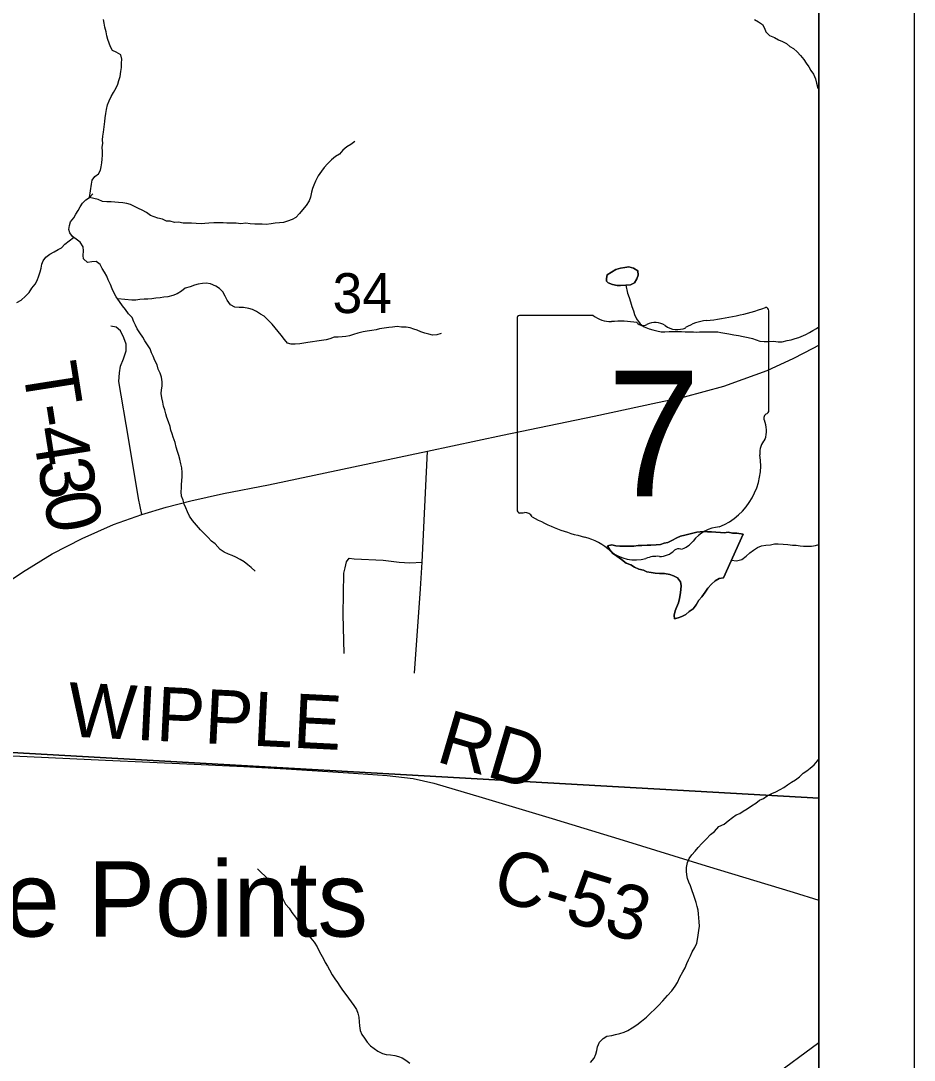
# Model space of a CAD drawing. Extents: x -20.2 to 34, y 0 to 22.
# Drawn here: x 8.064 to 9, y 15.546 to 16.636 of the extents above; entities that cross this region are included whole.
import ezdxf

# ---------------------------------------------------------------- set-up
doc = ezdxf.new("R2010")
doc.units = 0
for name, color, linetype in [('Default', 7, 'Continuous'), ('GM_X_County_Road', 7, 'Continuous'), ('GM_X_County_Road_Text', 7, 'Continuous'), ('GM_X_Minor_River', 7, 'Continuous'), ('GM_X_Section_Text', 7, 'Continuous'), ('GM_X_State_Location', 7, 'Continuous'), ('GM_X_State_Route', 7, 'Continuous'), ('GM_X_State_Shield', 7, 'Continuous'), ('GM_X_Township_Road', 7, 'Continuous'), ('GM_X_Township_Road_Text', 7, 'Continuous'), ('GM_X_Unincorporated_Text', 7, 'Continuous'), ('SH_Cut_Line', 7, 'Continuous'), ('SH_Data', 7, 'Continuous')]:
    doc.layers.add(name, color=color, linetype=linetype)

msp = doc.modelspace()

# ---------------------------------------------------------------- linework, layer by layer
at = {"layer": 'Default'}
msp.add_lwpolyline([(7.8018, 14.8755), (8.7518, 14.8242), (8.8043, 14.8205), (8.8307, 14.8199), (8.9, 14.8176), (8.9, 20.9)], dxfattribs=at)
for points in [[(8.9, 15.8211), (8.9, 16.8537), (7.92, 16.8975), (7.8624, 15.8798)], [(8.9, 15.3734), (8.9, 15.8211), (7.8624, 15.8798), (7.7985, 14.8753), (8.8697, 14.8191)]]:
    msp.add_lwpolyline(points, close=True, dxfattribs=at)
at = {"layer": 'GM_X_County_Road'}
for points in [[(7.897, 15.8728), (7.9034, 15.8722), (7.9138, 15.8722), (7.9584, 15.8698), (8.0532, 15.8653), (8.0554, 15.8652), (8.1524, 15.8608), (8.2454, 15.8566), (8.2975, 15.854), (8.3417, 15.8516), (8.407, 15.8476), (8.4477, 15.8447), (8.4747, 15.8414), (8.4965, 15.8366), (8.547, 15.8215), (8.6207, 15.7995), (8.695, 15.7768), (8.7819, 15.7502), (8.8731, 15.7225), (8.9, 15.7139)], [(8.8507, 15.5286), (8.9, 15.565)]]:
    msp.add_lwpolyline(points, dxfattribs=at)
at = {"layer": 'GM_X_Minor_River'}
for points in [[(8.1357, 16.4506), (8.1377, 16.4644), (8.1384, 16.4686), (8.1411, 16.4724), (8.1452, 16.4751), (8.1471, 16.4789), (8.1478, 16.4827), (8.1485, 16.4869), (8.1488, 16.4907), (8.1491, 16.4949), (8.1491, 16.4987), (8.149, 16.5032), (8.1494, 16.507), (8.1493, 16.5108), (8.1497, 16.5146), (8.1504, 16.5188), (8.1511, 16.5245), (8.1518, 16.5299), (8.1521, 16.534), (8.1528, 16.5386), (8.1535, 16.5428), (8.1546, 16.5474), (8.1561, 16.5516), (8.1583, 16.5562), (8.1609, 16.5604), (8.1635, 16.5653), (8.1654, 16.5692), (8.1665, 16.573), (8.1679, 16.5772), (8.1686, 16.5825), (8.169, 16.5867), (8.1693, 16.5912), (8.1696, 16.5954), (8.1684, 16.6), (8.1634, 16.6029), (8.1596, 16.6044), (8.1577, 16.6082), (8.1561, 16.612), (8.1549, 16.6161), (8.1538, 16.6199), (8.153, 16.6241), (8.1518, 16.629), (8.1509, 16.6332), (8.1501, 16.637)], [(8.8326, 16.6368), (8.8368, 16.6346), (8.8411, 16.6316), (8.843, 16.6278), (8.8446, 16.624), (8.8484, 16.6203), (8.8534, 16.6181), (8.8576, 16.6158), (8.8621, 16.614), (8.866, 16.6118), (8.8698, 16.6088), (8.8736, 16.6065), (8.8774, 16.6032), (8.8809, 16.5994), (8.8844, 16.5949), (8.8867, 16.5911), (8.8894, 16.5874), (8.8917, 16.5836), (8.8944, 16.5798), (8.8964, 16.5749), (8.8976, 16.5704), (8.8991, 16.5651), (8.9, 16.5637)], [(8.4136, 16.5092), (8.4094, 16.5061), (8.4053, 16.5034), (8.4011, 16.4999), (8.3978, 16.4957), (8.3936, 16.4934), (8.3891, 16.4899), (8.385, 16.4857), (8.3816, 16.4819), (8.3786, 16.478), (8.3753, 16.473), (8.3723, 16.4677), (8.3708, 16.4635), (8.3693, 16.4597), (8.3682, 16.4559), (8.3672, 16.4509), (8.3657, 16.4471), (8.3627, 16.4421), (8.359, 16.4375), (8.3556, 16.4337), (8.3519, 16.4294), (8.3481, 16.4275), (8.3432, 16.4255), (8.339, 16.4243), (8.3348, 16.4239), (8.3303, 16.4235), (8.3261, 16.4227), (8.3208, 16.4222), (8.3166, 16.4225), (8.3128, 16.4225), (8.309, 16.4225), (8.3041, 16.4228), (8.2995, 16.4235), (8.2942, 16.423), (8.2893, 16.4237), (8.2851, 16.4237), (8.2794, 16.4236), (8.2756, 16.4239), (8.2711, 16.4239), (8.2658, 16.4238), (8.2608, 16.4234), (8.2566, 16.4233), (8.2525, 16.4229), (8.2475, 16.4232), (8.2426, 16.4235), (8.2384, 16.4235), (8.2339, 16.4234), (8.2289, 16.4245), (8.2247, 16.4244), (8.2202, 16.4255), (8.2164, 16.4258), (8.2122, 16.4277), (8.2072, 16.4288), (8.2034, 16.4302), (8.1996, 16.4317), (8.1954, 16.4347), (8.1908, 16.4373), (8.187, 16.4388), (8.1828, 16.441), (8.1786, 16.4432), (8.1748, 16.4443), (8.1706, 16.445), (8.166, 16.4453), (8.1622, 16.4457), (8.1584, 16.446), (8.1539, 16.446), (8.1493, 16.4463), (8.1448, 16.4485), (8.1357, 16.4506)], [(8.3094, 16.0588), (8.3052, 16.0626), (8.3014, 16.0656), (8.2976, 16.0686), (8.2934, 16.0712), (8.2888, 16.0735), (8.285, 16.0753), (8.2812, 16.0765), (8.2766, 16.0787), (8.2724, 16.0817), (8.2674, 16.0874), (8.2636, 16.0904), (8.2598, 16.0945), (8.256, 16.0979), (8.2521, 16.1021), (8.2479, 16.107), (8.2437, 16.1119), (8.2403, 16.1164), (8.2383, 16.121), (8.2364, 16.1251), (8.2349, 16.1289), (8.2337, 16.1331), (8.2321, 16.1376), (8.2317, 16.1418), (8.2321, 16.146), (8.232, 16.1498), (8.2324, 16.1536), (8.2327, 16.1581), (8.2327, 16.1623), (8.2323, 16.1672), (8.2315, 16.1714), (8.2303, 16.1763), (8.2292, 16.1801), (8.228, 16.1843), (8.2264, 16.1889), (8.2253, 16.1938), (8.2233, 16.1991), (8.2222, 16.2029), (8.221, 16.2067), (8.2202, 16.2105), (8.2183, 16.2154), (8.2167, 16.2199), (8.2156, 16.2237), (8.2144, 16.2279), (8.2132, 16.2317), (8.2124, 16.2358), (8.2113, 16.2404), (8.2108, 16.2449), (8.2112, 16.2487), (8.2119, 16.2526), (8.2119, 16.2571), (8.2111, 16.262), (8.2095, 16.2662), (8.2076, 16.2707), (8.2064, 16.2749), (8.2041, 16.2795), (8.2022, 16.284), (8.2007, 16.2878), (8.1991, 16.292), (8.1964, 16.2961), (8.1937, 16.3003), (8.1914, 16.3041), (8.1884, 16.3086), (8.1857, 16.3127), (8.1837, 16.3165), (8.1822, 16.3203), (8.1803, 16.3245), (8.1764, 16.3286), (8.1734, 16.3332), (8.1703, 16.3369), (8.1672, 16.3415), (8.1634, 16.3464), (8.1615, 16.3502), (8.1592, 16.3547), (8.1576, 16.3593), (8.1553, 16.3642), (8.1537, 16.368), (8.1514, 16.3721), (8.1488, 16.3759), (8.1468, 16.3801), (8.1426, 16.3835), (8.1381, 16.383), (8.1335, 16.3823), (8.1293, 16.386), (8.1289, 16.3898), (8.1293, 16.3944), (8.1288, 16.3989), (8.1258, 16.4035), (8.1216, 16.4069), (8.1177, 16.4095), (8.1151, 16.4133), (8.1139, 16.417), (8.1146, 16.4212), (8.1157, 16.425), (8.1191, 16.4292), (8.1214, 16.4331), (8.1236, 16.4369), (8.1259, 16.4407), (8.1281, 16.4445), (8.1319, 16.4479), (8.1357, 16.4506)], [(8.1357, 16.4506), (8.1391, 16.4544)], [(8.0639, 16.343), (8.0685, 16.3472), (8.0722, 16.3507), (8.0752, 16.3553), (8.0786, 16.3595), (8.0809, 16.3636), (8.0824, 16.3682), (8.0838, 16.3724), (8.085, 16.3762), (8.0857, 16.3804), (8.0872, 16.3842), (8.0898, 16.388), (8.094, 16.3911), (8.0985, 16.3934), (8.1027, 16.3961), (8.1064, 16.3976), (8.1098, 16.4014), (8.119, 16.4086)], [(8.6979, 16.3586), (8.6922, 16.3581), (8.6885, 16.3581), (8.6839, 16.3592), (8.6793, 16.3611), (8.6775, 16.3629), (8.6774, 16.3656), (8.6781, 16.3694), (8.6827, 16.3721), (8.6872, 16.3748), (8.6921, 16.3764), (8.6967, 16.3772), (8.701, 16.3776), (8.7058, 16.3765), (8.7104, 16.3735), (8.7108, 16.3689), (8.7093, 16.3651), (8.7067, 16.3609), (8.7025, 16.359), (8.6979, 16.3586)], [(8.6872, 16.3748), (8.6827, 16.3721), (8.6781, 16.3694), (8.6774, 16.3656), (8.6775, 16.3629), (8.6793, 16.3611), (8.6839, 16.3592), (8.6885, 16.3581), (8.6922, 16.3581), (8.6979, 16.3586)], [(8.6979, 16.3586), (8.7025, 16.359), (8.7067, 16.3609), (8.7093, 16.3651), (8.7108, 16.3689), (8.7104, 16.3735), (8.7058, 16.3765), (8.701, 16.3776), (8.6967, 16.3772), (8.6921, 16.3764), (8.6872, 16.3748)], [(8.5043, 16.3078), (8.4997, 16.3066), (8.4952, 16.3062), (8.4914, 16.3073), (8.4872, 16.3084), (8.483, 16.3096), (8.4792, 16.3114), (8.4754, 16.3125), (8.4716, 16.3137), (8.4674, 16.3144), (8.4625, 16.3147), (8.4579, 16.3151), (8.4533, 16.3147), (8.4492, 16.3143), (8.4446, 16.3135), (8.4397, 16.3127), (8.4359, 16.3119), (8.4314, 16.3111), (8.4268, 16.3103), (8.4226, 16.3095), (8.4169, 16.3083), (8.4124, 16.3068), (8.4082, 16.3056), (8.4044, 16.3048), (8.4003, 16.3044), (8.3961, 16.304), (8.3919, 16.304), (8.3874, 16.3024), (8.3836, 16.3012), (8.3787, 16.3005), (8.3737, 16.3), (8.3692, 16.2992), (8.3646, 16.2985), (8.3604, 16.2977), (8.3559, 16.2969), (8.3513, 16.2968), (8.3468, 16.2968), (8.343, 16.2979), (8.3399, 16.3017), (8.3365, 16.3062), (8.3334, 16.31), (8.3303, 16.3138), (8.3269, 16.3176), (8.3223, 16.3225), (8.3188, 16.3262), (8.315, 16.3281), (8.3105, 16.3311), (8.3066, 16.333), (8.3025, 16.3341), (8.2971, 16.3352), (8.2926, 16.3352), (8.288, 16.3355), (8.2834, 16.3378), (8.28, 16.343), (8.2777, 16.3472), (8.2754, 16.3514), (8.2719, 16.3551), (8.2681, 16.3574), (8.2624, 16.36), (8.2578, 16.3607), (8.254, 16.3603), (8.2495, 16.3595), (8.2457, 16.3587), (8.2412, 16.3568), (8.2359, 16.3553), (8.2321, 16.3522), (8.2275, 16.3495), (8.223, 16.3476), (8.2177, 16.3464), (8.2135, 16.346), (8.2097, 16.3452), (8.2052, 16.3448), (8.201, 16.3444), (8.1968, 16.344), (8.193, 16.3439), (8.1885, 16.3435), (8.1843, 16.3427), (8.1801, 16.3427), (8.1652, 16.3441)], [(8.6979, 16.3586), (8.6995, 16.3502), (8.7011, 16.3457), (8.7026, 16.3411), (8.7042, 16.3362), (8.7057, 16.3317), (8.7069, 16.3279), (8.7088, 16.3233), (8.7127, 16.318), (8.7169, 16.315), (8.7222, 16.3128), (8.726, 16.3117), (8.7302, 16.3106), (8.7348, 16.3098), (8.7386, 16.3095), (8.7431, 16.3099), (8.7473, 16.3099), (8.7511, 16.31), (8.756, 16.31), (8.7598, 16.3096), (8.7644, 16.3097), (8.7685, 16.3097), (8.7723, 16.3093), (8.7748, 16.3097), (8.7803, 16.3098), (8.7856, 16.3098), (8.7902, 16.3098), (8.794, 16.3095), (8.7973, 16.3089), (8.8016, 16.3084), (8.8058, 16.3077), (8.8111, 16.3066), (8.8157, 16.3059), (8.8206, 16.3048), (8.8259, 16.3036), (8.8305, 16.3025), (8.8343, 16.3011), (8.8381, 16.2999), (8.8427, 16.2996), (8.8476, 16.2996), (8.8525, 16.2997), (8.8575, 16.2993), (8.8617, 16.2993), (8.867, 16.3005), (8.8711, 16.3013), (8.8753, 16.3025), (8.8791, 16.3036), (8.8863, 16.3067), (8.8901, 16.309), (8.8938, 16.311), (8.8976, 16.3133), (8.9, 16.3148)], [(8.0594, 16.3403), (8.0639, 16.343)], [(8.8206, 16.0977), (8.8141, 16.0985), (8.8096, 16.0988), (8.805, 16.0996), (8.8008, 16.0991), (8.797, 16.0995), (8.7921, 16.0998), (8.7875, 16.1002), (8.7834, 16.1002), (8.7796, 16.1005), (8.7758, 16.1001), (8.772, 16.0997), (8.7678, 16.0985), (8.7636, 16.0977), (8.7595, 16.0966), (8.7549, 16.0954), (8.7511, 16.0939), (8.7458, 16.0908), (8.7417, 16.0888), (8.7379, 16.0881), (8.7341, 16.0869), (8.7296, 16.0865), (8.7239, 16.0861), (8.7201, 16.086), (8.7144, 16.0856), (8.7106, 16.0856), (8.706, 16.0852), (8.7011, 16.0851), (8.6961, 16.0851), (8.6916, 16.0851), (8.6874, 16.0854), (8.6832, 16.0865), (8.6787, 16.0854), (8.681, 16.0812), (8.6841, 16.0774), (8.6883, 16.0744), (8.6932, 16.071), (8.6982, 16.0673)], [(8.8206, 16.0977), (8.8001, 16.052), (8.7955, 16.0513), (8.7913, 16.0486), (8.7876, 16.0451), (8.7838, 16.0409), (8.7808, 16.0367), (8.7774, 16.0321), (8.7744, 16.0283), (8.7714, 16.0234), (8.7684, 16.0195), (8.7642, 16.0165), (8.7605, 16.0134), (8.7563, 16.0115), (8.7525, 16.0099), (8.7487, 16.0088), (8.7483, 16.0126), (8.7494, 16.0171), (8.7509, 16.0209), (8.7528, 16.0255), (8.7539, 16.0301), (8.7546, 16.0339), (8.7553, 16.0392), (8.7557, 16.0438), (8.7549, 16.0475), (8.7518, 16.0517), (8.7476, 16.0539), (8.7438, 16.0554), (8.7381, 16.0565), (8.7332, 16.0565), (8.7286, 16.0569), (8.7244, 16.0576), (8.7199, 16.0583), (8.7161, 16.0598), (8.7115, 16.0609), (8.7069, 16.0632), (8.7031, 16.0654), (8.6982, 16.0673), (8.6932, 16.071), (8.6883, 16.0744), (8.6841, 16.0774), (8.681, 16.0812), (8.6787, 16.0854), (8.6832, 16.0865), (8.6874, 16.0854), (8.6916, 16.0851), (8.6961, 16.0851), (8.7011, 16.0851), (8.706, 16.0852), (8.7106, 16.0856), (8.7144, 16.0856), (8.7201, 16.086), (8.7239, 16.0861), (8.7296, 16.0865), (8.7341, 16.0869), (8.7379, 16.0881), (8.7417, 16.0888), (8.7458, 16.0908), (8.7511, 16.0939), (8.7549, 16.0954), (8.7595, 16.0966), (8.7636, 16.0977), (8.7678, 16.0985), (8.772, 16.0997), (8.7758, 16.1001), (8.7796, 16.1005), (8.7834, 16.1002), (8.7875, 16.1002), (8.7921, 16.0998), (8.797, 16.0995), (8.8008, 16.0991), (8.805, 16.0996), (8.8096, 16.0988), (8.8141, 16.0985), (8.8206, 16.0977)], [(8.6982, 16.0673), (8.7031, 16.0654), (8.7069, 16.0632), (8.7115, 16.0609), (8.7161, 16.0598), (8.7199, 16.0583), (8.7244, 16.0576), (8.7286, 16.0569), (8.7332, 16.0565), (8.7381, 16.0565), (8.7438, 16.0554), (8.7476, 16.0539), (8.7518, 16.0517), (8.7549, 16.0475), (8.7557, 16.0438), (8.7553, 16.0392), (8.7546, 16.0339), (8.7539, 16.0301), (8.7528, 16.0255), (8.7509, 16.0209), (8.7494, 16.0171), (8.7483, 16.0126), (8.7487, 16.0088), (8.7525, 16.0099), (8.7563, 16.0115), (8.7605, 16.0134), (8.7642, 16.0165), (8.7684, 16.0195), (8.7714, 16.0234), (8.7744, 16.0283), (8.7774, 16.0321), (8.7808, 16.0367), (8.7838, 16.0409), (8.7876, 16.0451), (8.7913, 16.0486), (8.7955, 16.0513), (8.8001, 16.052), (8.8206, 16.0977)], [(8.8084, 16.0705), (8.8136, 16.0697), (8.8193, 16.0712), (8.8238, 16.0746), (8.8276, 16.0781), (8.8314, 16.0808), (8.8359, 16.0838), (8.8401, 16.0854), (8.8446, 16.0862), (8.8492, 16.0866), (8.8537, 16.0874), (8.8575, 16.0874), (8.8628, 16.0871), (8.8674, 16.0867), (8.8723, 16.086), (8.8761, 16.086), (8.8803, 16.0853), (8.8841, 16.0849), (8.8887, 16.085), (8.8925, 16.085), (8.8966, 16.0858), (8.9, 16.0868)], [(8.6674, 15.5566), (8.6681, 15.5604), (8.67, 15.5653), (8.6741, 15.5692), (8.6779, 15.5715), (8.6832, 15.5723), (8.687, 15.5731), (8.6915, 15.5742), (8.6961, 15.5758), (8.6999, 15.5773), (8.7044, 15.5804), (8.7093, 15.5835), (8.7142, 15.5873), (8.7195, 15.5915), (8.7237, 15.5957), (8.7282, 15.5999), (8.732, 15.6038), (8.7365, 15.6087), (8.7414, 15.6141), (8.7459, 15.6191), (8.7493, 15.624), (8.7519, 15.6278), (8.7545, 15.6332), (8.7575, 15.6389), (8.7598, 15.6431), (8.7616, 15.6477), (8.7635, 15.6515), (8.7654, 15.6557), (8.7672, 15.6598), (8.7702, 15.6644), (8.7721, 15.669), (8.7728, 15.6728), (8.7736, 15.6774), (8.7743, 15.6823), (8.775, 15.6869), (8.7746, 15.6914), (8.7742, 15.6956), (8.7738, 15.6998), (8.7734, 15.7036), (8.7726, 15.7074), (8.7714, 15.7115), (8.7702, 15.7157), (8.7687, 15.7199), (8.7671, 15.724), (8.7656, 15.729), (8.7637, 15.7328), (8.7625, 15.7369), (8.7617, 15.7407), (8.7613, 15.7445), (8.7613, 15.7483), (8.7624, 15.7536), (8.7642, 15.7578), (8.7669, 15.7616), (8.7703, 15.7655), (8.7737, 15.7693), (8.7774, 15.7735), (8.7819, 15.7781), (8.7865, 15.783), (8.7906, 15.7861), (8.7951, 15.7911), (8.8008, 15.7938), (8.805, 15.7972), (8.8095, 15.8007), (8.8133, 15.8034), (8.8171, 15.8049), (8.8208, 15.8072), (8.825, 15.8099), (8.8295, 15.813), (8.8341, 15.8157), (8.8378, 15.8187), (8.842, 15.8207), (8.8458, 15.8233), (8.8507, 15.8257), (8.8549, 15.8276), (8.8594, 15.8299), (8.8632, 15.8322), (8.8673, 15.8349), (8.8715, 15.8376), (8.8757, 15.8403), (8.8798, 15.8433), (8.8836, 15.8472), (8.8874, 15.8495), (8.8911, 15.8525), (8.8953, 15.856), (8.8987, 15.8602), (8.9, 15.8618)], [(8.3117, 15.747), (8.3155, 15.7429), (8.3197, 15.7391), (8.3236, 15.7349), (8.3262, 15.7308), (8.3301, 15.7278), (8.3331, 15.7236), (8.3358, 15.7191), (8.3381, 15.7153), (8.3412, 15.71), (8.3447, 15.7058), (8.3477, 15.7013), (8.3516, 15.6964), (8.3546, 15.6915), (8.3573, 15.6877), (8.3608, 15.6824), (8.3642, 15.6786), (8.3677, 15.6741), (8.3711, 15.6699), (8.3742, 15.665), (8.3761, 15.6612), (8.3781, 15.6575), (8.3807, 15.6525), (8.3827, 15.6488), (8.385, 15.645), (8.3873, 15.6412), (8.39, 15.6359), (8.3927, 15.6317), (8.3954, 15.6276), (8.398, 15.6238), (8.4007, 15.6196), (8.4042, 15.6151), (8.4069, 15.6113), (8.4099, 15.6076), (8.4126, 15.6038), (8.4153, 15.5996), (8.4169, 15.5958), (8.418, 15.5913), (8.4184, 15.5867), (8.4185, 15.5825), (8.4193, 15.5776), (8.4212, 15.5731), (8.4239, 15.5693), (8.4266, 15.5651), (8.43, 15.5614), (8.4338, 15.5587), (8.4377, 15.5557), (8.4426, 15.5535), (8.4464, 15.5524), (8.451, 15.552), (8.4555, 15.5513), (8.4593, 15.5502), (8.4632, 15.5487), (8.4673, 15.5464), (8.4712, 15.5434)], [(8.6606, 15.544), (8.6644, 15.5486), (8.6663, 15.5528), (8.6674, 15.5566)]]:
    msp.add_lwpolyline(points, dxfattribs=at)
at = {"layer": 'GM_X_State_Route'}
msp.add_lwpolyline([(8.0484, 16.0464), (8.0653, 16.0578), (8.0963, 16.0769), (8.128, 16.0932), (8.1609, 16.1077), (8.1904, 16.1183), (8.2161, 16.1258), (8.2418, 16.1324), (8.2762, 16.1403), (8.3232, 16.1494), (8.4897, 16.1845), (8.5686, 16.2014), (8.6645, 16.2214), (8.7311, 16.2357), (8.7592, 16.2416), (8.8003, 16.2528), (8.8208, 16.2599), (8.8459, 16.2691), (8.874, 16.2821), (8.8942, 16.2924), (8.9, 16.2957)], dxfattribs=at)
at = {"layer": 'GM_X_State_Shield'}
for p, q in [((8.8475, 16.2271), (8.8475, 16.3318)), ((8.5838, 16.3234), (8.5838, 16.1232)), ((8.6636, 16.3268), (8.5864, 16.3268)), ((8.8475, 16.2271), (8.8475, 16.2271))]:
    msp.add_line(p, q, dxfattribs=at)
for centre, radius, start, end in [((8.7536, 16.5996), 0.2796, 275.8445, 288.9065), ((8.8446, 16.3322), 0.00294, 351.8621, 97.738), ((8.5868, 16.3238), 0.00305, 98.1301, 188.1301), ((8.682, 16.35), 0.0296, 231.6195, 271.1119), ((8.6918, 16.2144), 0.1064, 80.4867, 94.9883), ((8.716, 16.3248), 0.00855, 219.7921, 297.1024), ((8.7285, 16.3017), 0.0178, 54.4667, 119.1411), ((8.7892, 16.2657), 0.0563, 97.3462, 120.7689), ((8.7515, 16.3334), 0.0214, 233.8562, 294.8282), ((8.8468, 16.2194), 0.00454, 107.944, 210.337), ((8.8444, 16.2267), 0.00314, 289.6038, 7.7341), ((8.8179, 16.2062), 0.0273, 340.033, 23.6496), ((8.858, 16.1833), 0.0198, 136.8065, 186.9296), ((8.7692, 16.1699), 0.0699, 292.3089, 8.9858), ((8.5869, 16.1228), 0.00308, 171.9584, 258.3066), ((8.5873, 16.1433), 0.0235, 267.339, 280.6039), ((8.5921, 16.1117), 0.00848, 29.7484, 93.2717), ((8.6992, 16.2915), 0.2019, 240.4129, 257.1985), ((8.7987, 16.0671), 0.0383, 94.4031, 142.5768), ((8.639, 16.0333), 0.0632, 47.1842, 75.836), ((8.7502, 16.1038), 0.0226, 282.8732, 323.2771), ((8.7073, 16.1107), 0.0401, 230.7004, 286.2918), ((8.7334, 16.0957), 0.0214, 268.777, 315.5493), ((8.7528, 16.0763), 0.00601, 65.7517, 132.6484), ((8.7305, 16.0415), 0.0329, 85.6951, 111.2099)]:
    msp.add_arc(centre, radius, start, end, dxfattribs=at)
at = {"layer": 'GM_X_Township_Road'}
for points in [[(8.1904, 16.1183), (8.1868, 16.1351), (8.1766, 16.1982), (8.1663, 16.2577), (8.167, 16.2667), (8.1681, 16.2735), (8.1711, 16.2812), (8.174, 16.2898), (8.1742, 16.2966), (8.1716, 16.3034), (8.1681, 16.3107), (8.1637, 16.3144), (8.1578, 16.3156)], [(8.4764, 15.9521), (8.4826, 16.0402), (8.4842, 16.0682), (8.4897, 16.1845)], [(8.4021, 16.0567), (8.4035, 16.0624), (8.4048, 16.0686), (8.4079, 16.0723), (8.4129, 16.0719), (8.4434, 16.0703), (8.4602, 16.0682), (8.4714, 16.0675), (8.4842, 16.0682)], [(8.4025, 15.9724), (8.4016, 16.0133), (8.4021, 16.0567)]]:
    msp.add_lwpolyline(points, dxfattribs=at)
at = {"layer": 'SH_Cut_Line'}
msp.add_lwpolyline([(5.7735, 14.1), (8.9, 14.1), (8.9, 20.9), (2.1, 20.9), (2.1, 14.1), (5.3953, 14.1), (5.7268, 14.1076)], close=True, dxfattribs=at)
at = {"layer": 'SH_Data'}
for p, q in [((9, 21), (9, 14)), ((8.9, 20.9), (8.9, 14.1))]:
    msp.add_line(p, q, dxfattribs=at)

# ---------------------------------------------------------------- texts
at = {"layer": 'GM_X_County_Road_Text'}
for s, rotation, p in [('WIPPLE', 357.1467, (8.1119, 15.8857)), ('RD', 343.5814, (8.4973, 15.8598)), ('C-53', 343.0776, (8.5551, 15.7166))]:
    msp.add_text(s, height=0.05682, rotation=rotation, dxfattribs=at).set_placement(p)
at = {"layer": 'GM_X_Section_Text'}
msp.add_text('34', height=0.04186, rotation=0, dxfattribs=at).set_placement((8.3904, 16.3293))
at = {"layer": 'GM_X_State_Location'}
for s in ['s', 'r']:
    msp.add_text(s, height=0.000189, dxfattribs=at).set_placement((8.7127, 16.21))
msp.add_text('7', height=0.000189, rotation=0, dxfattribs=at).set_placement((8.6842, 16.1962))
at = {"layer": 'GM_X_State_Shield'}
msp.add_text('7', height=0.1318, dxfattribs=at).set_placement((8.6779, 16.1373))
at = {"layer": 'GM_X_Township_Road_Text'}
for s, rotation, p in [('T', 278.9593, (8.0651, 16.2731)), ('-', 278.9838, (8.0717, 16.2311)), ('4', 279.0586, (8.0754, 16.2079)), ('3', 279.3952, (8.0809, 16.173)), ('0', 280.5507, (8.0869, 16.1373))]:
    msp.add_text(s, height=0.0568, rotation=rotation, dxfattribs=at).set_placement(p)
at = {"layer": 'GM_X_Unincorporated_Text'}
msp.add_text('Five Points', height=0.078977, rotation=0, dxfattribs=at).set_placement((7.905, 15.6759))

doc.saveas('drawing.dxf')
